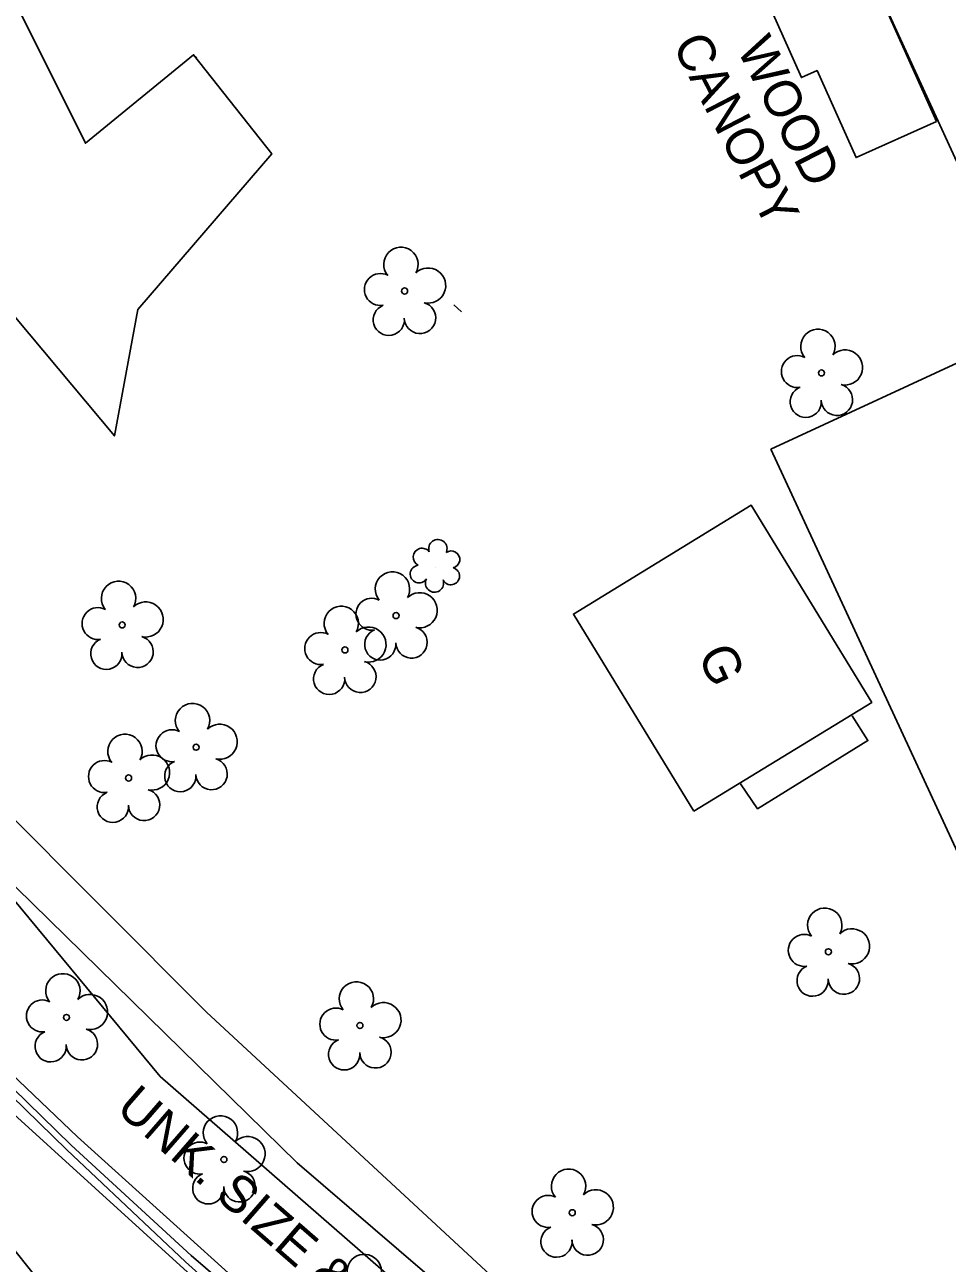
# Model space of a CAD drawing. Extents: x 1534145 to 1537876, y 509021 to 513201.
# Drawn here: x 1536346.3 to 1536446, y 511445.5 to 511579.4 of the extents above; entities that cross this region are included whole.
import ezdxf

# ---------------------------------------------------------------- set-up
doc = ezdxf.new("R2010")
doc.units = 0
for name, color, linetype in [('Exist Building', 7, 'Continuous'), ('Exist Building Text', 7, 'Continuous'), ('Exist Horizontal Alignment', 7, 'Continuous'), ('Exist Horizontal Baseline Alignment', 7, 'Continuous'), ('Exist Other Culture Area Outline', 7, 'Continuous'), ('Exist Other Culture Fence Line', 7, 'Continuous'), ('Exist Right of Way Line', 7, 'Continuous'), ('Exist Roads EOP', 7, 'Continuous'), ('Exist Utilities Telephone UG Cable', 7, 'Continuous'), ('Exist Utilities Telephone UG FO SUE', 7, 'Continuous'), ('Exist Utilities TV UG Cable', 7, 'Continuous'), ('Exist Utilities TV UG Cable Text', 7, 'Continuous'), ('Exist Utilities Water UG Line SUE', 7, 'Continuous'), ('Exist Vegetation Shrub CELL', 7, 'Continuous'), ('Exist Vegetation Tree CELL', 7, 'Continuous'), ('Exist Vegetation Woods Line', 7, 'Continuous')]:
    doc.layers.add(name, color=color, linetype=linetype)

msp = doc.modelspace()

# ---------------------------------------------------------------- linework, layer by layer
at = {"layer": 'Exist Building'}
for points in [[(1536444.89, 511568.93), (1536437.47, 511585.51), (1536427.07, 511580.86), (1536430.28, 511573.69), (1536431.97, 511574.45), (1536436.18, 511565.04)], [(1536426.98, 511533.49), (1536447.19, 511489.86), (1536470.71, 511500.76), (1536450.5, 511544.38)], [(1536418.63, 511494.36), (1536405.61, 511515.68), (1536424.85, 511527.44), (1536437.88, 511506.12)]]:
    msp.add_lwpolyline(points, close=True, dxfattribs=at)
at = {"layer": 'Exist Horizontal Alignment'}
msp.add_arc((1537414.41, 512634.1), 1600, 223.9944, 229.0503, dxfattribs=at)
at = {"layer": 'Exist Horizontal Baseline Alignment'}
msp.add_line((1536066.28, 511797.6), (1536449.44, 511315.8), dxfattribs=at)
at = {"layer": 'Exist Other Culture Area Outline'}
msp.add_lwpolyline([(1536435.75, 511504.66), (1536437.46, 511502), (1536425.54, 511494.62), (1536423.68, 511497.31)], dxfattribs=at)
at = {"layer": 'Exist Other Culture Fence Line'}
msp.add_lwpolyline([(1536559.59, 511559.04), (1536544.69, 511585.14), (1536518.03, 511632.02), (1536473.07, 511609.73), (1536435.1, 511590.69), (1536475.67, 511502.32), (1536499.5, 511512.38)], dxfattribs=at)
at = {"layer": 'Exist Right of Way Line'}
msp.add_lwpolyline([(1536145.81, 511737.79), (1536209.6, 511636.11), (1536268.44, 511561.44), (1536375.73, 511456.33), (1536489.24, 511358.86)], dxfattribs=at)
at = {"layer": 'Exist Roads EOP'}
msp.add_lwpolyline([(1536631.58, 511437.38), (1536631.26, 511437.24), (1536618.41, 511431.15), (1536595.54, 511419.22), (1536573.28, 511404.96), (1536551.98, 511389.82), (1536530.94, 511372.53), (1536511.9, 511355.24), (1536502.63, 511347.19), (1536496.64, 511344.02), (1536490.92, 511343.71), (1536482.45, 511344.56), (1536475.44, 511348.14), (1536453.49, 511366.6), (1536410.8, 511403.51), (1536369.08, 511439.8), (1536328.72, 511476.49)], dxfattribs=at)
at = {"layer": 'Exist Utilities Telephone UG Cable'}
for points in [[(1536322.91, 511485.98), (1536351.29, 511458.25), (1536364.29, 511446.31), (1536392.48, 511422.05), (1536399.17, 511416.05), (1536420.96, 511399.93), (1536466.03, 511362), (1536478.71, 511349.03), (1536485.14, 511341.66), (1536522.76, 511310.8), (1536559.53, 511281.7), (1536602.6, 511247.35), (1536625.89, 511227.16), (1536628.82, 511221.42), (1536662.2, 511194.51), (1536688.11, 511173.43)], [(1536322.34, 511485.55), (1536350.85, 511457.73), (1536363.66, 511445.63), (1536391.12, 511420.96), (1536397.58, 511413.79), (1536417.92, 511395.46), (1536462.92, 511357.5), (1536474.02, 511346.78), (1536481.16, 511338.26), (1536519.63, 511307.4), (1536556.25, 511277.86), (1536598.92, 511243.15), (1536627.63, 511219.93), (1536661, 511193.02), (1536686.78, 511171.87)]]:
    msp.add_lwpolyline(points, dxfattribs=at)
at = {"layer": 'Exist Utilities Telephone UG FO SUE'}
for p, q in [((1536339.83, 511498.78), (1536365.95, 511472.62)), ((1536365.95, 511472.62), (1536399.74, 511441.34))]:
    msp.add_line(p, q, dxfattribs=at)
at = {"layer": 'Exist Utilities TV UG Cable'}
for p, q in [((1536335.77, 511496.06), (1536360.94, 511465.66)), ((1536360.94, 511465.66), (1536393.97, 511436.9))]:
    msp.add_line(p, q, dxfattribs=at)
at = {"layer": 'Exist Utilities Water UG Line SUE'}
for p, q in [((1536323.51, 511486.29), (1536352.01, 511459.14)), ((1536352.01, 511459.14), (1536379.42, 511434.44))]:
    msp.add_line(p, q, dxfattribs=at)
at = {"layer": 'Exist Vegetation Shrub CELL'}
msp.add_line((1536390.73, 511520.71), (1536390.73, 511520.71), dxfattribs=at)
for centre, radius, start, end in [((1536390.96, 511522.75), 0.99, 334.8391, 200.4717), ((1536389.25, 511521.83), 0.968, 35.8908, 245.4216), ((1536392.4, 511521.57), 0.929, 284.4567, 126.0861), ((1536388.93, 511520), 0.955, 95.1099, 327.9534), ((1536390.6, 511519.02), 0.984, 151.2797, 21.387), ((1536392.37, 511519.78), 0.937, 204.9913, 73.4601)]:
    msp.add_arc(centre, radius, start, end, dxfattribs=at)
at = {"layer": 'Exist Vegetation Tree CELL'}
for p, q in [((1536387.36, 511550.61), (1536387.36, 511550.61)), ((1536432.44, 511541.75), (1536432.44, 511541.75)), ((1536386.44, 511515.51), (1536386.44, 511515.51)), ((1536356.82, 511514.5), (1536356.82, 511514.5)), ((1536380.91, 511511.8), (1536380.91, 511511.8)), ((1536364.82, 511501.28), (1536364.82, 511501.28)), ((1536357.52, 511497.95), (1536357.52, 511497.95)), ((1536433.19, 511479.16), (1536433.19, 511479.16)), ((1536350.8, 511472.06), (1536350.8, 511472.06)), ((1536382.53, 511471.19), (1536382.53, 511471.19)), ((1536367.83, 511456.7), (1536367.83, 511456.7)), ((1536405.49, 511450.94), (1536405.49, 511450.94))]:
    msp.add_line(p, q, dxfattribs=at)
for centre in [(1536387.36, 511550.61), (1536432.44, 511541.75), (1536386.44, 511515.51), (1536356.82, 511514.5), (1536380.91, 511511.8), (1536364.82, 511501.28), (1536357.52, 511497.95), (1536433.19, 511479.16), (1536350.8, 511472.06), (1536382.53, 511471.19), (1536367.83, 511456.7), (1536405.49, 511450.94)]:
    msp.add_circle(centre, 0.326, dxfattribs=at)
for centre, radius, start, end in [((1536386.97, 511553.49), 1.86, 330.1651, 219.7134), ((1536389.91, 511551.2), 1.9, 257.1011, 134.1999), ((1536384.75, 511550.77), 1.73, 62.6636, 279.3457), ((1536385.65, 511547.49), 1.69, 111.5671, 6.231), ((1536389.03, 511547.71), 1.7, 181.2822, 74.56), ((1536432.06, 511544.62), 1.86, 330.1651, 219.7134), ((1536429.84, 511541.9), 1.73, 62.6636, 279.3457), ((1536434.99, 511542.34), 1.9, 257.1011, 134.1999), ((1536430.74, 511538.63), 1.69, 111.5671, 6.231), ((1536434.11, 511538.85), 1.7, 181.2822, 74.56), ((1536386.05, 511518.38), 1.86, 330.1651, 219.7134), ((1536356.43, 511517.37), 1.86, 330.1651, 219.7134), ((1536359.37, 511515.09), 1.9, 257.1011, 134.1999), ((1536383.83, 511515.66), 1.73, 62.6636, 279.3457), ((1536388.99, 511516.09), 1.9, 257.1011, 134.1999), ((1536354.21, 511514.65), 1.73, 62.6636, 279.3457), ((1536380.52, 511514.67), 1.86, 330.1651, 219.7134), ((1536383.46, 511512.38), 1.9, 257.1011, 134.1999), ((1536388.11, 511512.61), 1.7, 181.2822, 74.56), ((1536355.11, 511511.38), 1.69, 111.5671, 6.231), ((1536358.49, 511511.6), 1.7, 181.2822, 74.56), ((1536378.3, 511511.95), 1.73, 62.6636, 279.3457), ((1536384.73, 511512.39), 1.69, 111.5671, 6.231), ((1536379.2, 511508.67), 1.69, 111.5671, 6.231), ((1536382.58, 511508.9), 1.7, 181.2822, 74.56), ((1536364.43, 511504.16), 1.86, 330.1651, 219.7134), ((1536367.37, 511501.87), 1.9, 257.1011, 134.1999), ((1536357.13, 511500.83), 1.86, 330.1651, 219.7134), ((1536362.21, 511501.44), 1.73, 62.6636, 279.3457), ((1536354.91, 511498.11), 1.73, 62.6636, 279.3457), ((1536360.06, 511498.54), 1.9, 257.1011, 134.1999), ((1536363.11, 511498.16), 1.69, 111.5671, 6.231), ((1536366.49, 511498.38), 1.7, 181.2822, 74.56), ((1536359.19, 511495.05), 1.7, 181.2822, 74.56), ((1536355.81, 511494.83), 1.69, 111.5671, 6.231), ((1536432.8, 511482.03), 1.86, 330.1651, 219.7134), ((1536430.58, 511479.31), 1.73, 62.6636, 279.3457), ((1536435.74, 511479.75), 1.9, 257.1011, 134.1999), ((1536434.86, 511476.26), 1.7, 181.2822, 74.56), ((1536350.41, 511474.94), 1.86, 330.1651, 219.7134), ((1536431.48, 511476.04), 1.69, 111.5671, 6.231), ((1536382.15, 511474.06), 1.86, 330.1651, 219.7134), ((1536348.19, 511472.22), 1.73, 62.6636, 279.3457), ((1536353.35, 511472.65), 1.9, 257.1011, 134.1999), ((1536379.93, 511471.34), 1.73, 62.6636, 279.3457), ((1536385.08, 511471.77), 1.9, 257.1011, 134.1999), ((1536349.09, 511468.94), 1.69, 111.5671, 6.231), ((1536352.47, 511469.16), 1.7, 181.2822, 74.56), ((1536384.21, 511468.29), 1.7, 181.2822, 74.56), ((1536380.83, 511468.07), 1.69, 111.5671, 6.231), ((1536367.45, 511459.57), 1.86, 330.1651, 219.7134), ((1536370.38, 511457.29), 1.9, 257.1011, 134.1999), ((1536365.23, 511456.85), 1.73, 62.6636, 279.3457), ((1536366.13, 511453.58), 1.69, 111.5671, 6.231), ((1536369.51, 511453.8), 1.7, 181.2822, 74.56), ((1536405.1, 511453.81), 1.86, 330.1651, 219.7134), ((1536402.88, 511451.09), 1.73, 62.6636, 279.3457), ((1536408.04, 511451.53), 1.9, 257.1011, 134.1999), ((1536403.79, 511447.82), 1.69, 111.5671, 6.231), ((1536407.16, 511448.04), 1.7, 181.2822, 74.56), ((1536383, 511444.59), 1.86, 330.1651, 219.7134)]:
    msp.add_arc(centre, radius, start, end, dxfattribs=at)
at = {"layer": 'Exist Vegetation Woods Line'}
for points in [[(1536364.55, 511576.16), (1536373, 511565.43), (1536358.52, 511548.6), (1536355.99, 511534.94), (1536336.01, 511558.77), (1536332.84, 511549.1), (1536313.82, 511551.08), (1536307.55, 511548.5), (1536253.81, 511613.18), (1536228.12, 511640.97), (1536207.73, 511675.11), (1536230.48, 511698.35), (1536246.44, 511712.1), (1536224.35, 511724.34), (1536209.33, 511733.76), (1536195.78, 511706.5), (1536177.81, 511692.48), (1536173.01, 511708.97), (1536159.67, 511734.26)], [(1536516.96, 511640.03), (1536463.65, 511609.65), (1536434.4, 511620.27), (1536421.78, 511609.84), (1536404.1, 511618.79), (1536384.74, 511607.1), (1536353.58, 511620.21), (1536341.21, 511620.37), (1536339.37, 511593.55), (1536352.85, 511566.58), (1536364.55, 511576.16), (1536364.88, 511575.84)], [(1536392.7, 511549.13), (1536393.53, 511548.34)]]:
    msp.add_lwpolyline(points, dxfattribs=at)

# ---------------------------------------------------------------- texts
at = {"layer": 'Exist Building Text'}
for s, rotation, p in [('CANOPY', 297.2824, (1536416.26, 511577.23)), ('WOOD', 297.2824, (1536423.22, 511576.82)), ('G', 294.8536, (1536418.99, 511511.28))]:
    msp.add_text(s, height=4, rotation=rotation, dxfattribs=at).set_placement(p)
at = {"layer": 'Exist Utilities TV UG Cable Text'}
msp.add_text('UNK. SIZE & MATERIAL', height=4, rotation=318.9517, dxfattribs=at).set_placement((1536356, 511462.01))

doc.saveas('drawing.dxf')
